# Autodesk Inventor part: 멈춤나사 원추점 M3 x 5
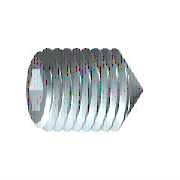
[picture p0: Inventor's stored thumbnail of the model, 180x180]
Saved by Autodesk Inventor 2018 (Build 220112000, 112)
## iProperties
IsCustomPart: 1
Created: 2012-02
Part Number: 멈춤나사 원추점 M3 x 5
Material: 강철, 연강
Description: 6각 소켓 머리 없는 멈춤 나사
Document SubType Name: Modeling
Standard: KS B 1028
Designer: mduedu
Standards Organization: KS
Language: ko-KR
Size Designation: 원추점 M3x5
Categories: <MemberInstance><Categories><Category DisplayName="조임쇠" InternalName="e4da775c-781d-43d5-af7c-5136215cf5a6" Mnemonic="FSTN"><Category DisplayName="볼트" InternalN
Density: 7.85 g/cm^3
Appearance: 노란색
Mass: 0.193416 g
Surface Area: 0.605428 cm^2
Volume: 0.0246389 cm^3
Author: mduedu
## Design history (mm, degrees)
sketch "스케치1"
  geometry: L1 (0, 0)-(2.5, 0); L2 (5, 0.866)-(5, 1.5); L3 (5, 1.5)-(0, 1.5); L4 (5, 0.866)-(3, 0.866); L5 (3, 0.866)-(2.5, 0); L6 (0, -0.3)-(0, 1.8) reference; L7 (0, 1.5)-(0, 0)
  constraints: 13 end point, 3 parallel, 1 collinear, 1 perpendicular, 1 point on line
  dimensions: "d0" = 2 distance of L2.start L4.end (= INTI); "d1" = 60 deg angle of L5 L1; "d2" = 3 diameter of L3 L1 (= NND); "d3" = 1.73205 diameter of L4 L1 (= 1.1547 x SW); "d5" = 5 distance from line of L2 L3.end (= NLG)
revolve "본체" sketch "스케치1" stored, may be unused: angle "d6" = 90 deg
sketch "스케치2"
  geometry: L1 (-0.433, 0.75)-(0.433, 0.75); L2 (0.433, 0.75)-(0.866, 0); L3 (0.866, 0)-(0.433, -0.75); L4 (0.433, -0.75)-(-0.433, -0.75); L5 (-0.433, -0.75)-(-0.866, 0); L6 (-0.866, 0)-(-0.433, 0.75); 3 further points
  constraints: 12 end point, 1 coincident, 1 horizontal, 13 other
extrude "슬롯" join sketch "스케치2" taper "d7" = 0 deg; stored distance "d21" = 10
workaxis "Work Axis1"
workplane "Work Plane1"
sketch "스케치4"
  geometry: L1 (-5, 1.193)-(-4.693, 1.5) reference; L2 (-4.693, 1.5)-(-1.35, 1.5) reference; L3 (-1.35, 1.5)-(0, 0.15) reference; L4 (0, 0.15)-(0, -0.15) reference; L5 (0, -0.15)-(-1.35, -1.5) reference; L6 (-1.35, -1.5)-(-4.693, -1.5) reference; L7 (-4.693, -1.5)-(-5, -1.193) reference; L8 (-5, -1.193)-(-5, -0.75) reference; L9 (-5, -0.75)-(-2.933, -0.75) reference; L10 (-2.933, -0.75)-(-2.5, 0) reference; L11 (-2.5, 0)-(-2.933, 0.75) reference; L12 (-2.933, 0.75)-(-5, 0.75) reference; L13 (-5, 0.75)-(-5, 1.193) reference; L14 (0, 0.15)-(0.15, 0); L15 (0, -0.15)-(0.15, 0); 1 further point
  constraints: 4 end point, 1 parallel, 1 perpendicular
  node "절단 모서리 투영1"
node "작업점1"
body "Solid1"
feature "스레드" dims "d12" = 5 (= NLG), "d13" = 0
chamfer "모따기1" distance "d8" = 1.35 (computed from NND, SPD, FAWI); stored, may be unused: angle "d9" = 45 deg (= FAWI), second distance "d34" = 1.35 (computed from NND, SPD, FAWI)
chamfer "모따기2" distance "d10" = 0.30673 (= -0.5 x GD1 + 0.5 x NND); stored, may be unused: angle "d11" = 45 deg (= FAWI), second distance "d35" = 0.30673 (= -0.5 x GD1 + 0.5 x NND)
other parameters: "NND" = 3 [user parameter; used in 5 equation terms], "NLG" = 5 [user parameter; used in 2 equation terms], "INTI" = 2 [user parameter; used in 1 equation term], "FAWI" = 45 deg [user parameter; used in 4 equation terms], "SW" = 1.5 [user parameter; used in 2 equation terms], "GD1" = 2.38655 (= THREADDIA - 1.2269 x PTC) [user parameter; used in 2 equation terms], "d4" = 0, "FAWI1" = 45 deg [user parameter], "SPD" = 0.3 [user parameter; used in 2 equation terms], "d36" = 0, "d37" = 0, "GUL" = 0.30673 (= 0.61345 x PTC) [user parameter], "TOA" = 30 deg [user parameter], "THREADDIA" = 3 [user parameter; used in 1 equation term], "PTC" = 0.5 [user parameter; used in 4 equation terms], "GAL" = 0.30673 (= 0.61345 x PTC) [user parameter], "E0" = 1.7325 (= 1.155 x SW) [user parameter]
